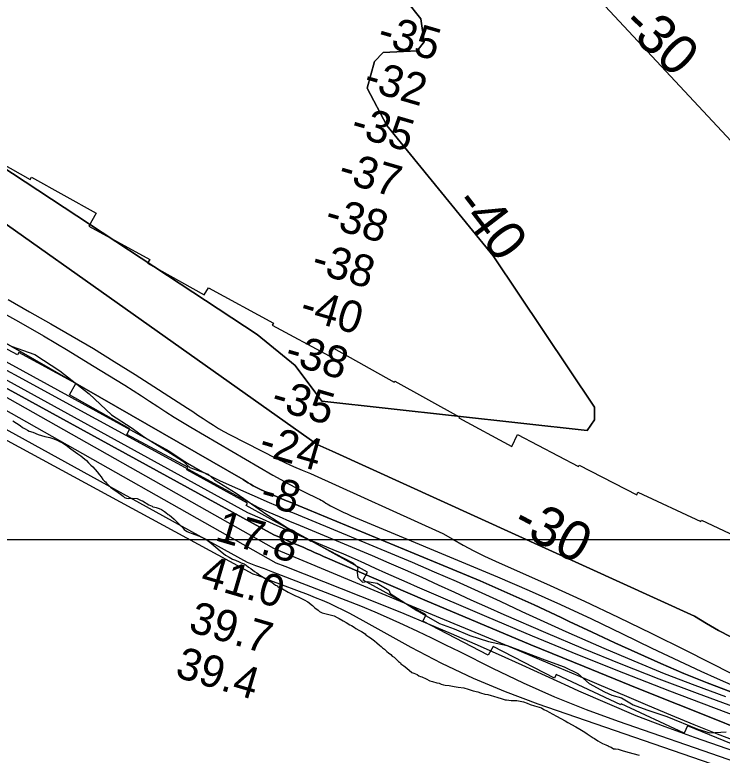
# Model space of a CAD drawing. Extents: x 3263578 to 3301413, y 764927 to 798602.
# Drawn here: x 3283343 to 3284833, y 781434 to 782995 of the extents above; entities that cross this region are included whole.
import ezdxf

# ---------------------------------------------------------------- set-up
doc = ezdxf.new("R2010")
doc.units = 0
for name, color, linetype in [('V-GRID-MAJR', 7, 'Continuous'), ('V-RIVR-EDGE', 7, 'Continuous'), ('V-RIVR-RANG', 7, 'Continuous'), ('V-RRAP-RVMT', 7, 'Continuous'), ('V-SITE-VEGE', 7, 'Continuous'), ('V-TOPO-DPTH', 7, 'Continuous'), ('V-TOPO-MAJR', 7, 'Continuous'), ('V-TOPO-MINR', 7, 'Continuous'), ('V-TOPO-MINR-IDEN', 7, 'Continuous'), ('V-TOPO-WATR', 7, 'Continuous')]:
    doc.layers.add(name, color=color, linetype=linetype)

msp = doc.modelspace()

# ---------------------------------------------------------------- linework, layer by layer
at = {"layer": 'V-GRID-MAJR'}
msp.add_spline([(3267730.5, 781891.4), (3270351, 781890.6), (3275592.2, 781889.4), (3280833.3, 781889.1), (3286074.5, 781889.4), (3291315.6, 781890.6), (3296556.8, 781892.5), (3299177.4, 781893.7)], degree=3, dxfattribs=at)
at = {"layer": 'V-RIVR-EDGE'}
msp.add_lwpolyline([(3283334.9, 782296.7), (3283384.8, 782278.7), (3283437.3, 782244.7), (3283498.9, 782195.9), (3283546.6, 782151.8), (3283587.8, 782125.2), (3283616.1, 782104.7), (3283670.3, 782071.1), (3283695.5, 782054.5), (3283711.1, 782041), (3283750.2, 782027), (3283763.2, 782014.4), (3283809.2, 781986.5), (3283873.4, 781941.5), (3283917.2, 781913.6), (3283993.2, 781872.1), (3284034.5, 781850.3), (3284054.9, 781839.8), (3284065.3, 781830.6), (3284063.5, 781819.3), (3284065.2, 781808.5), (3284075.2, 781798.9), (3284085.2, 781800.6), (3284106, 781796.6), (3284130.8, 781781.8), (3284133.4, 781775.3), (3284189.4, 781739.1), (3284237.5, 781711.5), (3284268.4, 781700.6), (3284301.4, 781686.6), (3284340.5, 781673.9), (3284379.6, 781665.6), (3284459.5, 781635.4), (3284499.9, 781620.5), (3284529, 781606.5), (3284552.8, 781585.6), (3284584.5, 781567.7), (3284600.1, 781560.7), (3284621, 781555), (3284645.3, 781540.1), (3284673.9, 781530.1), (3284716.1, 781515.6), (3284781.2, 781489.4), (3284806.4, 781481.5), (3284841.2, 781483.6)], dxfattribs=at)
at = {"layer": 'V-RRAP-RVMT'}
for points in [[(3283027.4, 782954.6), (3282990.8, 782859.1), (3282994.4, 782866.2), (3283132.1, 782789.4), (3283127.4, 782780.6), (3283245.2, 782715.2), (3283247.8, 782719.4), (3283375, 782647.9), (3283378, 782653), (3283513.8, 782577.2)], [(3283513.8, 782577.2), (3283498.5, 782549.7), (3283626.9, 782479.4), (3283622.3, 782471.2), (3283741.5, 782404.8), (3283750.4, 782419.8), (3283887.5, 782344.7), (3283884.5, 782340.8), (3284004.6, 782275.9), (3284013.8, 782292.2), (3284141.9, 782220.6), (3284142.9, 782222.9), (3284279, 782147.8), (3284277.7, 782145.6), (3284389.4, 782085.2), (3284401.3, 782110.1), (3284530, 782042.8), (3284531.6, 782045.7), (3284652.8, 781983.3), (3284655.4, 781989), (3284787.9, 781926.9), (3284789.3, 781929.8), (3284906, 781874.9)], [(3284898.9, 781439.5), (3284759.5, 781496.2), (3284752.6, 781480.8), (3284620, 781542.8), (3284619, 781540.4), (3284483.2, 781604.1), (3284479.4, 781596.7), (3284350, 781663.3), (3284340, 781645.2), (3284202.2, 781716.9), (3284209.1, 781729.9), (3284076.3, 781802.9), (3284085.8, 781819.8), (3283967.4, 781885.1), (3283967.2, 781884.5), (3283830, 781960.3), (3283833, 781965.5), (3283704.9, 782035.8), (3283707, 782041.1), (3283578.5, 782110.2), (3283584.6, 782122), (3283457.8, 782193.8), (3283471.3, 782217.6), (3283351.1, 782283), (3283348.2, 782278), (3283219.2, 782347.4)]]:
    msp.add_lwpolyline(points, dxfattribs=at)
at = {"layer": 'V-SITE-VEGE'}
for points in [[(3283338.1, 782139.1), (3283353.9, 782129.4), (3283359.1, 782125.2), (3283364.4, 782122.2), (3283369, 782119.2), (3283373.1, 782117.4), (3283380.7, 782115.5), (3283391.9, 782110.6), (3283405.9, 782106.3), (3283416.5, 782103.8), (3283422.9, 782101.9), (3283431.7, 782098.3), (3283437, 782095.2), (3283442.8, 782092.8), (3283451, 782088), (3283460.9, 782080.2), (3283475.4, 782069.4), (3283481.9, 782065.1), (3283485.9, 782061.5), (3283493.5, 782055.5), (3283497.5, 782050.8), (3283502.8, 782045.4), (3283506.8, 782042.4), (3283516.1, 782031.7), (3283521.3, 782025.1), (3283524.2, 782020.9), (3283528.2, 782015.6), (3283531.7, 782012), (3283533.5, 782010.8), (3283535.8, 782007.8), (3283544.5, 781999.4), (3283549.1, 781995.8), (3283560.2, 781988), (3283564.9, 781984.4), (3283570.7, 781980.2), (3283573.6, 781977.2), (3283577.7, 781976), (3283581.8, 781975.3), (3283590.1, 781975.8), (3283600.1, 781975.6), (3283608.8, 781971.4), (3283611.8, 781970.2), (3283624.6, 781962.3), (3283631.6, 781959.3), (3283633.4, 781958.1), (3283637.5, 781957.4), (3283640.4, 781956.2), (3283646.9, 781954.3), (3283651.5, 781951.9), (3283658, 781948.3), (3283660.9, 781945.9), (3283665.5, 781941.7), (3283668.4, 781940.5), (3283672.5, 781936.9), (3283678.3, 781932.1), (3283689.9, 781920.1), (3283694.6, 781916), (3283699.2, 781910), (3283702.1, 781908.2), (3283705.6, 781905.8), (3283708.5, 781904.6), (3283710.3, 781903.4), (3283714.4, 781902.1), (3283732, 781896), (3283744.8, 781889.9), (3283753.6, 781883.3), (3283766.4, 781873.1), (3283775.1, 781865.3), (3283786.7, 781855.7), (3283794.3, 781851.5), (3283801.3, 781847.8), (3283807.8, 781845.4), (3283815.4, 781841.7), (3283819.5, 781839.9), (3283825.9, 781837.5), (3283830, 781835), (3283835.2, 781830.8), (3283839.9, 781827.8), (3283847.5, 781821.8), (3283852.1, 781818.8), (3283859.1, 781813.4), (3283862.6, 781811.6), (3283866.1, 781809.2), (3283870.8, 781806.2), (3283879, 781801.3), (3283884.8, 781798.3), (3283891.8, 781792.9), (3283895.9, 781791.1), (3283897, 781789.3), (3283906.4, 781785), (3283918.6, 781777.8), (3283932.7, 781771.1), (3283940.9, 781767.5), (3283952, 781762), (3283959.6, 781757.2), (3283969.5, 781750), (3283974.7, 781745.2), (3283981.7, 781739.8)], [(3283981.7, 781739.8), (3283984.6, 781737.4), (3283989.8, 781734.3), (3283995.7, 781733.1), (3284001, 781731.2), (3284009.8, 781729.3), (3284015.1, 781728.1), (3284021.5, 781724.4), (3284026.2, 781722.6), (3284034.3, 781717.2), (3284040.8, 781714.2), (3284048.4, 781709.3), (3284051.9, 781707.5), (3284057.7, 781703.9), (3284061.2, 781701.5), (3284068.8, 781697.3), (3284072.9, 781694.8), (3284080.5, 781690), (3284082.2, 781688.2), (3284088.6, 781684), (3284092.1, 781681.6), (3284100.3, 781675), (3284105.5, 781671.4), (3284110.7, 781666), (3284114.2, 781663.6), (3284117.1, 781660.6), (3284121.2, 781657.6), (3284126.4, 781652.8), (3284129.9, 781649.8), (3284134.6, 781646.2), (3284137.5, 781643.2), (3284141.6, 781640.8), (3284145, 781637.2), (3284150.8, 781631.9), (3284154.9, 781628.8), (3284156.1, 781627.1), (3284157.8, 781625.3), (3284160.1, 781624.1), (3284161.9, 781622.9), (3284164.8, 781620.5), (3284168.9, 781616.9), (3284173.5, 781613.3), (3284179.3, 781608.5), (3284183.5, 781607.2), (3284189.9, 781604.2), (3284193.4, 781601.8), (3284197.5, 781600), (3284199.8, 781599.3), (3284209.2, 781595.1), (3284216.8, 781590.8), (3284222.6, 781589.6), (3284231.4, 781586.5), (3284236.7, 781585.8), (3284240.8, 781584), (3284245.5, 781582.8), (3284249, 781582.1), (3284257.9, 781581.4), (3284268.4, 781578.9), (3284276.6, 781577.6), (3284288.4, 781576.2), (3284297.8, 781573.7), (3284308.3, 781570), (3284317.7, 781567.6), (3284323.6, 781565.7), (3284333, 781563.2), (3284338.8, 781562.5), (3284346.4, 781560.1), (3284351.1, 781558.8), (3284359.9, 781555.7), (3284367, 781553.9), (3284375.8, 781550.8), (3284378.7, 781550.8), (3284388.1, 781549.4), (3284400.5, 781549.2), (3284414, 781546.7), (3284422.2, 781543.6), (3284428, 781541.2), (3284437.4, 781538.1), (3284442.1, 781536.9), (3284452.1, 781533.8), (3284457.3, 781530.7), (3284463.1, 781527.7), (3284468.4, 781524.7), (3284483.6, 781516.8), (3284501.7, 781506.5), (3284507.5, 781502.9), (3284524.5, 781493.8), (3284533.2, 781489), (3284543.2, 781483), (3284548.4, 781479.3), (3284561.2, 781470.9), (3284564.1, 781469.1), (3284571.1, 781464.3), (3284580.5, 781458.8), (3284587.5, 781456.4), (3284592.8, 781454), (3284594.5, 781452.2), (3284599.2, 781450.9), (3284603.9, 781447.9), (3284608, 781447.8), (3284613.9, 781446.6)], [(3284613.9, 781446.6), (3284622.1, 781444.1), (3284629.1, 781442.2), (3284644.4, 781437.9), (3284657.8, 781434.1)]]:
    msp.add_lwpolyline(points, dxfattribs=at)
at = {"layer": 'V-TOPO-DPTH'}
for points in [[(3284311.5, 783308.7), (3285283.6, 782265.6), (3285299.6, 782261.9), (3285316, 782259.1), (3285896.4, 782188.2), (3285953.1, 782181.1), (3286009.8, 782173.7), (3286066.5, 782166), (3286123.1, 782158.1), (3286230.7, 782142.6), (3286233.4, 782142.2), (3286236.2, 782141.6), (3286238.9, 782141.1), (3286241.6, 782140.4), (3286276.2, 782131.3), (3286296.1, 782125.5), (3286315.7, 782119), (3286334.9, 782111.6)], [(3284311.5, 783308.7), (3285283.6, 782265.6), (3285299.6, 782261.9), (3285316, 782259.1), (3285896.4, 782188.2), (3285953.1, 782181.1), (3286009.8, 782173.7), (3286066.5, 782166), (3286123.1, 782158.1), (3286230.7, 782142.6), (3286233.4, 782142.2), (3286236.2, 782141.6), (3286238.9, 782141.1), (3286241.6, 782140.4), (3286276.2, 782131.3), (3286296.1, 782125.5), (3286315.7, 782119), (3286334.9, 782111.6)], [(3282821.7, 782999.8), (3283853, 782321), (3283933.3, 782255.6), (3283989.4, 782180.4), (3284548.5, 782119), (3284563.5, 782141.5), (3284563.6, 782167.7), (3284350.5, 782487.2), (3284126, 782761.8), (3284084.9, 782840.7), (3284100, 782896.9), (3284118.9, 782915.6), (3284190.2, 782919.2), (3284205.2, 782937.9), (3284197.8, 782986.8), (3284167.9, 783024.4)], [(3284167.9, 783024.4), (3284197.8, 782986.8), (3284205.2, 782937.9), (3284190.2, 782919.2), (3284118.9, 782915.6), (3284100, 782896.9), (3284084.9, 782840.7), (3284126, 782761.8), (3284350.5, 782487.2), (3284563.6, 782167.7), (3284563.5, 782141.5), (3284548.5, 782119), (3283989.4, 782180.4), (3283933.3, 782255.6), (3283853, 782321), (3282821.7, 782999.8)], [(3284851.1, 781683.6), (3284825, 781697.3), (3284799.4, 781711.9), (3284774.5, 781727.5), (3284011.3, 782075.5), (3283979.6, 782089.4), (3282888, 782862.5)], [(3284851.1, 781683.6), (3284825, 781697.3), (3284799.4, 781711.9), (3284774.5, 781727.5), (3284011.3, 782075.5), (3283979.6, 782089.4), (3282888, 782862.5)], [(3284851.1, 781567.8), (3284801.4, 781586.5), (3284752.3, 781606.6), (3284703.5, 781627.5), (3284655, 781649.2), (3284606.7, 781671.2), (3284558.6, 781693.7), (3284510.6, 781716.4), (3284493.6, 781724.5), (3284437, 781750.9), (3284380.1, 781776.8), (3284322.8, 781801.7), (3284265.2, 781826), (3283919.4, 781968.7), (3283914.6, 781970.7), (3283909.7, 781972.7), (3283904.9, 781974.8), (3283900, 781976.9), (3283861.8, 781993.8), (3283856.1, 781996.5), (3283850.4, 781999.2), (3283844.9, 782002.2), (3283839.4, 782005.3), (3283834, 782008.5), (3283828.6, 782011.8), (3283823.3, 782015.1), (3282813.1, 782595.7)], [(3284851.1, 781567.8), (3284801.4, 781586.5), (3284752.3, 781606.6), (3284703.5, 781627.5), (3284655, 781649.2), (3284606.7, 781671.2), (3284558.6, 781693.7), (3284510.6, 781716.4), (3284493.6, 781724.5), (3284437, 781750.9), (3284380.1, 781776.8), (3284322.8, 781801.7), (3284265.2, 781826), (3283919.4, 781968.7), (3283914.6, 781970.7), (3283909.7, 781972.7), (3283904.9, 781974.8), (3283900, 781976.9), (3283861.8, 781993.8), (3283856.1, 781996.5), (3283850.4, 781999.2), (3283844.9, 782002.2), (3283839.4, 782005.3), (3283834, 782008.5), (3283828.6, 782011.8), (3283823.3, 782015.1), (3282813.1, 782595.7)], [(3282819.5, 782521.7), (3283856, 781956.5), (3283877.8, 781946.9), (3283899.6, 781937.3), (3283921.5, 781927.9), (3283943.4, 781918.6), (3284095.2, 781854.9), (3284130.2, 781840), (3284165, 781824.8), (3284199.7, 781809.3), (3284234.2, 781793.4), (3284268.8, 781777.6), (3284303.4, 781761.8), (3284338.1, 781746.4), (3284372.9, 781731.1), (3284460.8, 781692.8), (3284539.9, 781659.2), (3284619.4, 781626.5), (3284699.4, 781595.2), (3284779.8, 781564.8), (3285087.1, 781451.8)], [(3282819.5, 782521.7), (3283856, 781956.5), (3283877.8, 781946.9), (3283899.6, 781937.3), (3283921.5, 781927.9), (3283943.4, 781918.6), (3284095.2, 781854.9), (3284130.2, 781840), (3284165, 781824.8), (3284199.7, 781809.3), (3284234.2, 781793.4), (3284268.8, 781777.6), (3284303.4, 781761.8), (3284338.1, 781746.4), (3284372.9, 781731.1), (3284460.8, 781692.8), (3284539.9, 781659.2), (3284619.4, 781626.5), (3284699.4, 781595.2), (3284779.8, 781564.8), (3285087.1, 781451.8)], [(3284854.1, 781495.6), (3284826.1, 781506.7), (3284653.9, 781575.7), (3284541.7, 781621.1), (3284429.7, 781667), (3284318, 781713.9), (3284206.6, 781761.3), (3284001.6, 781849.5), (3283992.9, 781853.3), (3283984.3, 781857.1), (3283975.6, 781860.9), (3283967, 781864.8), (3283958.4, 781868.6), (3283949.7, 781872.5), (3283941.1, 781876.2), (3283932.4, 781880), (3283919.2, 781885.6), (3283903.9, 781892.2), (3283888.6, 781898.9), (3282782, 782505.4)], [(3283328.9, 782394.8), (3283373.8, 782369.1), (3283418.8, 782343.6), (3283463.6, 782317.9), (3283508.1, 782291.6), (3283552.1, 782264.5), (3283595.8, 782237), (3283706.6, 782165.6), (3283717.5, 782158.6), (3283728.4, 782151.4), (3283739.2, 782144.2), (3283750, 782137), (3283760.9, 782129.9), (3283771.9, 782123), (3283783.2, 782116.7), (3283794.7, 782110.5), (3283895.1, 782059.3), (3283912.5, 782050.8), (3283930, 782042.6), (3283947.7, 782035), (3283965.7, 782027.8), (3284244.6, 781901.7), (3284265, 781889.7), (3284287.2, 781877.2), (3284309.6, 781865.1), (3284332.4, 781853.9), (3284355.5, 781843.1), (3284470.6, 781791.7), (3284542.4, 781758.9), (3284613.9, 781725.4), (3284684.8, 781690.8), (3284755.4, 781655.5), (3284853.7, 781605.4)], [(3283328.9, 782394.8), (3283373.8, 782369.1), (3283418.8, 782343.6), (3283463.6, 782317.9), (3283508.1, 782291.6), (3283552.1, 782264.5), (3283595.8, 782237), (3283706.6, 782165.6), (3283717.5, 782158.6), (3283728.4, 782151.4), (3283739.2, 782144.2), (3283750, 782137), (3283760.9, 782129.9), (3283771.9, 782123), (3283783.2, 782116.7), (3283794.7, 782110.5), (3283895.1, 782059.3), (3283912.5, 782050.8), (3283930, 782042.6), (3283947.7, 782035), (3283965.7, 782027.8), (3284244.6, 781901.7), (3284265, 781889.7), (3284287.2, 781877.2), (3284309.6, 781865.1), (3284332.4, 781853.9), (3284355.5, 781843.1), (3284470.6, 781791.7), (3284542.4, 781758.9), (3284613.9, 781725.4), (3284684.8, 781690.8), (3284755.4, 781655.5), (3284853.7, 781605.4)]]:
    msp.add_lwpolyline(points, dxfattribs=at)
at = {"layer": 'V-TOPO-MAJR'}
msp.add_lwpolyline([(3282910.4, 782349.3), (3283832, 781841.1), (3283849.9, 781834.3), (3283867.8, 781827.5), (3283885.7, 781820.6), (3283903.6, 781813.7), (3284040.1, 781761), (3284070.6, 781748.8), (3284100.9, 781736.3), (3284131, 781723.2), (3284160.9, 781709.7), (3284190.7, 781695.7), (3284220.3, 781681.6), (3284249.8, 781667.2), (3284279.2, 781652.6), (3284349, 781617.5), (3284413.8, 781586.5), (3284479.3, 781557.3), (3284546, 781530.7), (3284613.4, 781505.8), (3285075.9, 781345.7)], dxfattribs=at)
at = {"layer": 'V-TOPO-MINR'}
for points in [[(3286334.9, 782111.6), (3286315.7, 782119), (3286296.1, 782125.5), (3286276.2, 782131.3), (3286241.6, 782140.4), (3286238.9, 782141.1), (3286236.2, 782141.6), (3286233.4, 782142.2), (3286230.7, 782142.6), (3286123.1, 782158.1), (3286066.5, 782166), (3286009.8, 782173.7), (3285953.1, 782181.1), (3285896.4, 782188.2), (3285316, 782259.1), (3285299.6, 782261.9), (3285283.6, 782265.6), (3284311.5, 783308.7)], [(3282821.7, 782999.8), (3283853, 782321), (3283933.3, 782255.6), (3283989.4, 782180.4), (3284548.5, 782119), (3284563.5, 782141.5), (3284563.6, 782167.7), (3284350.5, 782487.2), (3284126, 782761.8), (3284084.9, 782840.7), (3284100, 782896.9), (3284118.9, 782915.6), (3284190.2, 782919.2), (3284205.2, 782937.9), (3284197.8, 782986.8), (3284167.9, 783024.4)], [(3282888, 782862.5), (3283979.6, 782089.4), (3284011.3, 782075.5), (3284774.5, 781727.5), (3284799.4, 781711.9), (3284825, 781697.3), (3284851.1, 781683.6)], [(3282813.1, 782595.7), (3283823.3, 782015.1), (3283828.6, 782011.8), (3283834, 782008.5), (3283839.4, 782005.3), (3283844.9, 782002.2), (3283850.4, 781999.2), (3283856.1, 781996.5), (3283861.8, 781993.8), (3283900, 781976.9), (3283904.9, 781974.8), (3283909.7, 781972.7), (3283914.6, 781970.7), (3283919.4, 781968.7), (3284265.2, 781826), (3284322.8, 781801.7), (3284380.1, 781776.8), (3284437, 781750.9), (3284493.6, 781724.5), (3284510.6, 781716.4), (3284558.6, 781693.7), (3284606.7, 781671.2), (3284655, 781649.2), (3284703.5, 781627.5), (3284752.3, 781606.6), (3284801.4, 781586.5), (3284851.1, 781567.8)], [(3282838.2, 782529.8), (3283666.8, 782075.8), (3283679.8, 782067.1), (3283693, 782058.5), (3283706.2, 782050.2), (3283719.6, 782042), (3283733.1, 782034.1), (3283746.9, 782026.6), (3283760.9, 782019.6), (3283775, 782012.9), (3283878.4, 781966.9), (3283891.6, 781961.1), (3283904.8, 781955.4), (3283918, 781949.7), (3283931.2, 781944.2), (3284179.4, 781840.9), (3284226.1, 781821.1), (3284272.6, 781800.9), (3284318.8, 781780), (3284364.8, 781758.7), (3284410.8, 781737.2), (3284456.9, 781716), (3284503.1, 781695.2), (3284549.5, 781674.6), (3284583.1, 781659.9), (3284646.6, 781632.8), (3284710.5, 781606.6), (3284774.9, 781581.9), (3284839.7, 781558)], [(3282800.7, 782513.6), (3283832.9, 781945.9), (3283863.5, 781932.2), (3283894.3, 781918.6), (3283925.1, 781905.2), (3283956, 781892), (3284012.8, 781867.9), (3284035.1, 781858.4), (3284057.4, 781848.7), (3284079.5, 781838.8), (3284101.7, 781828.8), (3284123.8, 781818.8), (3284145.9, 781808.8), (3284168.1, 781799), (3284190.4, 781789.3), (3284336.6, 781726.3), (3284432.3, 781685.8), (3284528.3, 781646.2), (3284624.8, 781607.8), (3284721.6, 781570.2), (3285124.2, 781417.1)], [(3282782, 782505.4), (3283888.6, 781898.9), (3283903.9, 781892.2), (3283919.2, 781885.6), (3283932.4, 781880), (3283941.1, 781876.2), (3283949.7, 781872.5), (3283958.4, 781868.6), (3283967, 781864.8), (3283975.6, 781860.9), (3283984.3, 781857.1), (3283992.9, 781853.3), (3284001.6, 781849.5), (3284206.6, 781761.3), (3284318, 781713.9), (3284429.7, 781667), (3284541.7, 781621.1), (3284653.9, 781575.7), (3284826.1, 781506.7), (3284854.1, 781495.6)], [(3282744.5, 782489.1), (3283892.6, 781840), (3283911.6, 781832.5), (3284111.5, 781753.1), (3284161.8, 781732.7), (3284211.9, 781712), (3284261.8, 781690.8), (3284311.6, 781669.1), (3284361.1, 781647.1), (3284410.6, 781624.8), (3284460, 781602.4), (3284509.3, 781579.8), (3284530.2, 781570.2), (3284590.2, 781543.6), (3284650.8, 781518.2), (3284712.1, 781494.5), (3284773.8, 781472), (3285065, 781370.8)], [(3282888.8, 782434.7), (3283887.7, 781870.4), (3283894.2, 781867.7), (3284171.5, 781752.1), (3284247.4, 781720.3), (3284323.3, 781688.6), (3284399.2, 781656.7), (3284475, 781624.7), (3284528.9, 781601.9), (3284577.8, 781581.3), (3284626.6, 781560.6), (3284675.4, 781539.9), (3284724.2, 781519.1), (3284773.1, 781498.8), (3284822.3, 781479.2), (3284871.9, 781460.6)], [(3283328.9, 782394.8), (3283373.8, 782369.1), (3283418.8, 782343.6), (3283463.6, 782317.9), (3283508.1, 782291.6), (3283552.1, 782264.5), (3283595.8, 782237), (3283706.6, 782165.6), (3283717.5, 782158.6), (3283728.4, 782151.4), (3283739.2, 782144.2), (3283750, 782137), (3283760.9, 782129.9), (3283771.9, 782123), (3283783.2, 782116.7), (3283794.7, 782110.5), (3283895.1, 782059.3), (3283912.5, 782050.8), (3283930, 782042.6), (3283947.7, 782035), (3283965.7, 782027.8), (3284244.6, 781901.7), (3284265, 781889.7), (3284287.2, 781877.2), (3284309.6, 781865.1), (3284332.4, 781853.9), (3284355.5, 781843.1), (3284470.6, 781791.7), (3284542.4, 781758.9), (3284613.9, 781725.4), (3284684.8, 781690.8), (3284755.4, 781655.5), (3284853.7, 781605.4)], [(3283297.5, 782377.6), (3283350.3, 782348.3), (3283402.9, 782318.4), (3283454.9, 782287.6), (3283506.6, 782256.1), (3283574.4, 782214.1), (3283591.8, 782203.2), (3283609.2, 782192.1), (3283626.4, 782180.8), (3283643.6, 782169.5), (3283660.7, 782158.1), (3283678.1, 782147), (3283695.6, 782136.2), (3283713.2, 782125.7), (3283886.2, 782024.5), (3283902.7, 782015.1), (3283919.4, 782006), (3283936.4, 781997.2), (3283953.5, 781988.8), (3283980.8, 781975.7), (3283984.3, 781974), (3283987.7, 781972.1), (3283991, 781970.1), (3283994.3, 781968), (3283997.6, 781965.8), (3284000.9, 781963.8), (3284004.2, 781961.9), (3284007.7, 781960), (3284017.4, 781955), (3284025.8, 781950.8), (3284034.3, 781946.7), (3284042.8, 781942.8), (3284051.4, 781939.1), (3284359.4, 781809.9), (3284425.8, 781781.3), (3284492, 781752), (3284557.6, 781721.5), (3284622.8, 781690.3), (3284684.5, 781660.1), (3284718.7, 781643.6), (3284753.1, 781627.3), (3284787.6, 781611.3), (3284822.2, 781595.6), (3284857.1, 781580.6)], [(3282832.6, 782365.1), (3283843.9, 781816.9), (3283853.3, 781813.4), (3283862.7, 781809.9), (3283872.1, 781806.4), (3283881.5, 781802.8), (3283960.4, 781772.9), (3283975.3, 781767), (3283990.1, 781760.9), (3284004.7, 781754.4), (3284019.1, 781747.6), (3284033.5, 781740.5), (3284047.7, 781733.3), (3284061.9, 781725.8), (3284075.9, 781718.1), (3284176.7, 781662.1), (3284241.8, 781628.1), (3284308, 781596.4), (3284375.8, 781568.2), (3284444.6, 781542.5), (3285114.1, 781311.3)]]:
    msp.add_lwpolyline(points, dxfattribs=at)
at = {"layer": 'V-TOPO-WATR'}
msp.add_lwpolyline([(3282819.5, 782521.7), (3283856, 781956.5), (3283877.8, 781946.9), (3283899.6, 781937.3), (3283921.5, 781927.9), (3283943.4, 781918.6), (3284095.2, 781854.9), (3284130.2, 781840), (3284165, 781824.8), (3284199.7, 781809.3), (3284234.2, 781793.4), (3284268.8, 781777.6), (3284303.4, 781761.8), (3284338.1, 781746.4), (3284372.9, 781731.1), (3284460.8, 781692.8), (3284539.9, 781659.2), (3284619.4, 781626.5), (3284699.4, 781595.2), (3284779.8, 781564.8), (3285087.1, 781451.8)], dxfattribs=at)

# ---------------------------------------------------------------- texts
at = {"layer": 'V-RIVR-RANG'}
for s, rotation, p in [('-35', 343.7925, (3284103.3, 782933.9)), ('-32', 343.7925, (3284074.3, 782838.2)), ('-35', 343.7925, (3284047.3, 782741.9)), ('-37', 343.7925, (3284020.9, 782645.4)), ('-38', 343.7925, (3283992.4, 782549.6)), ('-38', 343.7925, (3283964.4, 782453.6)), ('-40', 343.7925, (3283939.7, 782356.6)), ('-38', 343.7925, (3283908.4, 782261.6)), ('-35', 343.7925, (3283879.4, 782165.9)), ('-24', 343.7925, (3283853.7, 782069.2)), ('-8', 343.7925, (3283855.9, 781964.4)), ('17.8', 343.6083, (3283761.8, 781888)), ('41.0', 343.6083, (3283731, 781792.9)), ('39.7', 343.6083, (3283705.8, 781696)), ('39.4', 343.6083, (3283677.8, 781600))]:
    msp.add_text(s, height=67, rotation=rotation, dxfattribs=at).set_placement(p)
at = {"layer": 'V-TOPO-MINR-IDEN'}
for s, rotation, p in [('-30', 316.7281, (3284617.7, 782970.4)), ('-40', 307.5037, (3284264.9, 782596.7)), ('-30', 332.1391, (3284386.8, 781910.9))]:
    msp.add_text(s, height=83, rotation=rotation, dxfattribs=at).set_placement(p)

doc.saveas('drawing.dxf')
